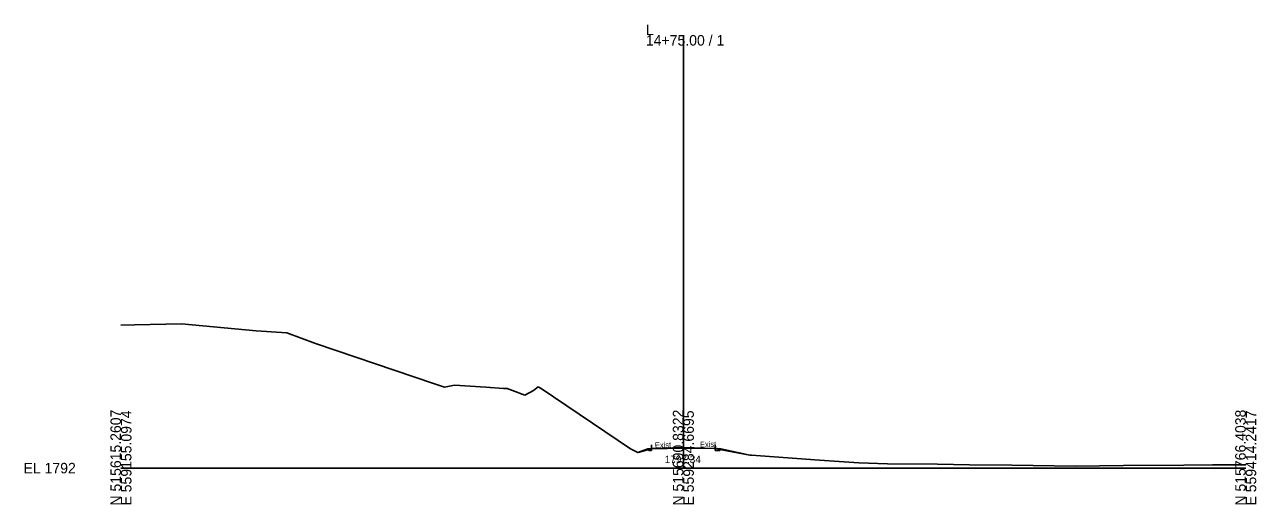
# Model space of a CAD drawing. Extents: x -26 to 1303, y -10 to 9545.
# Drawn here: x 974.3 to 1302.8, y 2990.3 to 3118.4 of the extents above; entities that cross this region are included whole.
import ezdxf

# ---------------------------------------------------------------- set-up
doc = ezdxf.new("R2010")
doc.units = 0
for name, color, linetype in [('Exist Cross Section Cell', 7, 'Continuous'), ('Exist XS Center Line Elevation Label', 7, 'Continuous'), ('Exist XS Ground Line', 7, 'Continuous'), ('Prop XS EOT Tick Mark', 7, 'Continuous'), ('Prop XS Finish Grade', 7, 'Continuous'), ('Prop XS Finish Grade Earthwork', 7, 'Continuous'), ('Prop XS Finish Grade Paved Shoulder', 7, 'Continuous'), ('Prop XS Finish Grade Pavement', 7, 'Continuous'), ('Prop XS Pvmt Edge Slope', 7, 'Continuous'), ('Prop XS SE Text', 7, 'Continuous'), ('Prop XS Subgrade Earthwork', 7, 'Continuous')]:
    doc.layers.add(name, color=color, linetype=linetype)

msp = doc.modelspace()

# ---------------------------------------------------------------- linework, layer by layer
at = {"layer": 'Exist Cross Section Cell'}
for p, q in [((1150, 3000), (1150, 3115.65)), ((1000, 3000), (1150, 3000)), ((1150, 3000), (1300, 3000))]:
    msp.add_line(p, q, dxfattribs=at)
at = {"layer": 'Exist XS Ground Line'}
for p, q in [((1000, 3038.18), (1003.63, 3038.25)), ((1003.63, 3038.25), (1016.19, 3038.55)), ((1016.19, 3038.55), (1036.1, 3036.66)), ((1036.1, 3036.66), (1044.2, 3036.1)), ((1044.2, 3036.1), (1051.87, 3033.31)), ((1051.87, 3033.31), (1083.62, 3022.52)), ((1083.62, 3022.52), (1086.28, 3021.62)), ((1086.28, 3021.62), (1086.75, 3021.71)), ((1086.75, 3021.71), (1088.98, 3022.13)), ((1088.98, 3022.13), (1097.36, 3021.6)), ((1097.36, 3021.6), (1101.99, 3021.3)), ((1101.99, 3021.3), (1102.99, 3021.25)), ((1102.99, 3021.25), (1104.44, 3020.73)), ((1104.44, 3020.73), (1107.71, 3019.45)), ((1107.71, 3019.45), (1109.99, 3020.69)), ((1109.99, 3020.69), (1111.26, 3021.73)), ((1111.26, 3021.73), (1112.04, 3021.22)), ((1112.04, 3021.22), (1135.88, 3005.18)), ((1135.88, 3005.18), (1137.87, 3004.17)), ((1137.87, 3004.17), (1138.32, 3004.29)), ((1138.32, 3004.29), (1141.66, 3005.2)), ((1141.66, 3005.2), (1145.72, 3005.27)), ((1145.72, 3005.27), (1150.12, 3005.34)), ((1150.12, 3005.34), (1155.83, 3005.29)), ((1155.83, 3005.29), (1158.28, 3005.28)), ((1158.28, 3005.28), (1167.76, 3003.48)), ((1167.76, 3003.48), (1168.15, 3003.44)), ((1168.15, 3003.44), (1186.3, 3002.09)), ((1186.3, 3002.09), (1196.78, 3001.39)), ((1196.78, 3001.39), (1204.45, 3001.17)), ((1204.45, 3001.17), (1217.81, 3001.01)), ((1217.81, 3001.01), (1226.29, 3000.84)), ((1226.29, 3000.84), (1237.66, 3000.77)), ((1237.66, 3000.77), (1254.58, 3000.56)), ((1254.58, 3000.56), (1267.41, 3000.66)), ((1267.41, 3000.66), (1283.53, 3000.82)), ((1283.53, 3000.82), (1291.16, 3000.86)), ((1291.16, 3000.86), (1300, 3000.85))]:
    msp.add_line(p, q, dxfattribs=at)
at = {"layer": 'Prop XS EOT Tick Mark'}
for p, q in [((1141.54, 3005.21), (1141.54, 3006.21)), ((1158.49, 3005.24), (1158.49, 3006.24))]:
    msp.add_line(p, q, dxfattribs=at)
at = {"layer": 'Prop XS Finish Grade'}
for p, q in [((1141.54, 3005.21), (1140.51, 3005.13)), ((1158.98, 3005.22), (1160.03, 3005.14))]:
    msp.add_line(p, q, dxfattribs=at)
at = {"layer": 'Prop XS Finish Grade Earthwork'}
for p, q in [((1140.51, 3005.13), (1137.87, 3004.17)), ((1160.03, 3005.14), (1167.76, 3003.48))]:
    msp.add_line(p, q, dxfattribs=at)
at = {"layer": 'Prop XS Finish Grade Paved Shoulder'}
msp.add_line((1158.49, 3005.24), (1158.98, 3005.22), dxfattribs=at)
at = {"layer": 'Prop XS Finish Grade Pavement'}
for p, q in [((1141.54, 3005.21), (1150, 3005.47)), ((1150, 3005.47), (1158.49, 3005.24))]:
    msp.add_line(p, q, dxfattribs=at)
at = {"layer": 'Prop XS Pvmt Edge Slope'}
for p, q in [((1141.54, 3005.21), (1140.98, 3004.65)), ((1158.98, 3005.22), (1159.54, 3004.64))]:
    msp.add_line(p, q, dxfattribs=at)
at = {"layer": 'Prop XS Subgrade Earthwork'}
for p, q in [((1140.98, 3004.65), (1140.51, 3005.13)), ((1141.54, 3004.67), (1140.98, 3004.65)), ((1141.54, 3004.67), (1141.54, 3005.17)), ((1158.49, 3004.7), (1158.49, 3005.21)), ((1158.49, 3004.7), (1159.54, 3004.64)), ((1159.54, 3004.64), (1160.03, 3005.14))]:
    msp.add_line(p, q, dxfattribs=at)

# ---------------------------------------------------------------- texts
at = {"layer": 'Exist Cross Section Cell'}
for s, p in [('L', (1140, 3115.65)), ('14+75.00 / 1', (1140, 3112.85)), ('EL 1792', (974, 2998.6))]:
    msp.add_text(s, height=2.8, dxfattribs=at).set_placement(p)
for s, p in [('N 515615.2607', (1000, 2990)), ('E 559155.0974', (1002.8, 2990)), ('N 515690.8322', (1150, 2990)), ('E 559284.6695', (1152.8, 2990)), ('N 515766.4038', (1300, 2990)), ('E 559414.2417', (1302.8, 2990))]:
    msp.add_text(s, height=2.8, rotation=90, dxfattribs=at).set_placement(p)
at = {"layer": 'Exist XS Center Line Elevation Label'}
msp.add_text('1797.34', height=2, dxfattribs=at).set_placement((1145.02, 3001.34))
at = {"layer": 'Prop XS SE Text'}
for p in [(1142.42, 3005.38), (1154.45, 3005.57)]:
    msp.add_text('Exist', height=1.5, rotation=1.3214, dxfattribs=at).set_placement(p)

doc.saveas('drawing.dxf')
